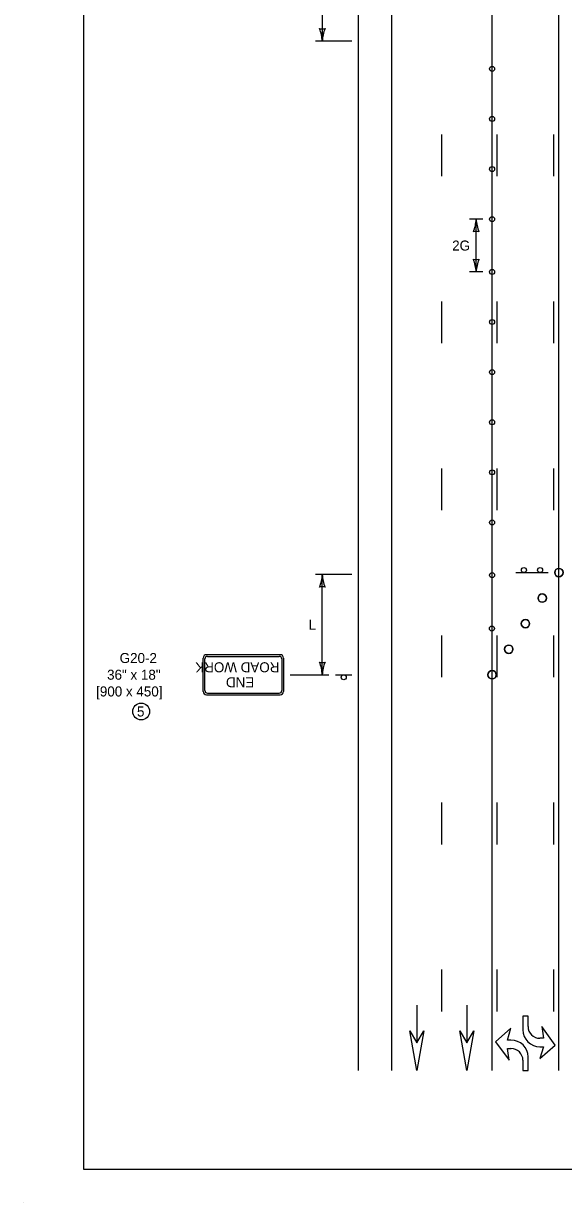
# Model space of a CAD drawing. Extents: x 49991.4 to 50021, y 49987.6 to 50011.4.
# Drawn here: x 49999.98 to 50003.21, y 49999.86 to 50006.92 of the extents above; entities that cross this region are included whole.
import ezdxf

# ---------------------------------------------------------------- set-up
doc = ezdxf.new("R2010")
doc.units = 0
for name, color, linetype in [('Level 1', 7, 'Continuous'), ('Level 2', 7, 'Continuous'), ('Level 3', 7, 'Continuous')]:
    doc.layers.add(name, color=color, linetype=linetype)

msp = doc.modelspace()

# ---------------------------------------------------------------- linework, layer by layer
at = {"layer": 'Level 1'}
for p, q in [((50001.9802, 50000.6526), (50001.9802, 50009.1708)), ((50002.1802, 50000.6526), (50002.1802, 50009.1708)), ((50002.7802, 50000.6526), (50002.7802, 50009.1708)), ((50003.1802, 50000.6526), (50003.1802, 50009.1708)), ((50002.4803, 50006.0059), (50002.4803, 50006.2559)), ((50002.8102, 50006.0059), (50002.8102, 50006.2559)), ((50003.1502, 50006.0059), (50003.1502, 50006.2559)), ((50002.4803, 50005.0059), (50002.4803, 50005.2559)), ((50002.8102, 50005.0059), (50002.8102, 50005.2559)), ((50003.1502, 50005.0059), (50003.1502, 50005.2559)), ((50002.4803, 50004.0059), (50002.4803, 50004.2559)), ((50002.8102, 50004.0059), (50002.8102, 50004.2559)), ((50003.1502, 50004.0059), (50003.1502, 50004.2559)), ((50002.9232, 50003.6329), (50003.0192, 50003.6329)), ((50003.0192, 50003.6329), (50003.1152, 50003.6329)), ((50002.4803, 50003.0059), (50002.4803, 50003.2559)), ((50002.8102, 50003.0059), (50002.8102, 50003.2559)), ((50003.1502, 50003.0059), (50003.1502, 50003.2559)), ((50001.0516, 50002.9214), (50001.0516, 50003.1214)), ((50001.0616, 50002.9264), (50001.0616, 50003.1164)), ((50001.0718, 50003.1415), (50001.5118, 50003.1415)), ((50001.0766, 50003.1314), (50001.5066, 50003.1314)), ((50001.5216, 50003.1164), (50001.5216, 50002.9264)), ((50001.5316, 50003.1214), (50001.5316, 50002.9214)), ((50001.8442, 50003.0214), (50001.9402, 50003.0214)), ((50001.0716, 50002.9014), (50001.5116, 50002.9014)), ((50001.0766, 50002.9114), (50001.5066, 50002.9114)), ((50002.4803, 50002.0059), (50002.4803, 50002.2559)), ((50002.4803, 50002.0059), (50002.4803, 50002.2559)), ((50002.8102, 50002.0059), (50002.8102, 50002.2559)), ((50002.8102, 50002.0059), (50002.8102, 50002.2559)), ((50003.1502, 50002.0059), (50003.1502, 50002.2559)), ((50003.1502, 50002.0059), (50003.1502, 50002.2559)), ((50002.4803, 50001.0059), (50002.4803, 50001.2559)), ((50002.4803, 50001.0059), (50002.4803, 50001.2559)), ((50002.8102, 50001.0059), (50002.8102, 50001.2559)), ((50002.8102, 50001.0059), (50002.8102, 50001.2559)), ((50003.1502, 50001.0059), (50003.1502, 50001.2559)), ((50003.1502, 50001.0059), (50003.1502, 50001.2559)), ((50002.3301, 50001.0427), (50002.3301, 50000.8168)), ((50002.3305, 50001.0427), (50002.3305, 50000.8168)), ((50002.6295, 50001.0427), (50002.6295, 50000.8168)), ((50002.6299, 50001.0427), (50002.6299, 50000.8168)), ((50002.9955, 50000.9766), (50002.9649, 50000.9766)), ((50002.9649, 50000.9766), (50002.9649, 50000.8957)), ((50002.9955, 50000.9159), (50002.9955, 50000.9766)), ((50002.8934, 50000.9053), (50002.8015, 50000.8244)), ((50002.873, 50000.8345), (50002.8934, 50000.9053)), ((50003.1588, 50000.8047), (50003.0772, 50000.9159)), ((50003.0772, 50000.9159), (50003.0874, 50000.8452)), ((50002.8934, 50000.8345), (50002.873, 50000.8345)), ((50003.0609, 50000.8502), (50003.0609, 50000.8502)), ((50003.0874, 50000.8452), (50003.067, 50000.8452)), ((50002.8015, 50000.8244), (50002.8832, 50000.7132)), ((50002.8832, 50000.7132), (50002.873, 50000.784)), ((50002.873, 50000.784), (50002.8934, 50000.784)), ((50002.8995, 50000.7789), (50002.8995, 50000.7789)), ((50003.067, 50000.7239), (50003.1588, 50000.8047)), ((50003.067, 50000.7946), (50003.0874, 50000.7946)), ((50003.0874, 50000.7946), (50003.067, 50000.7239)), ((50002.9649, 50000.7132), (50002.9649, 50000.6526)), ((50002.9955, 50000.6526), (50002.9955, 50000.7334)), ((50002.9649, 50000.6526), (50002.9955, 50000.6526)), ((49999.9766, 49999.8624), (49999.9766, 49999.8624))]:
    msp.add_line(p, q, dxfattribs=at)
for points in [[(50008.6146, 50011.2628), (50000.3356, 50011.2628), (50000.3356, 50000.0624), (50008.6146, 50000.0624)], [(50002.3721, 50000.8891), (50002.3305, 50000.6526), (50002.2885, 50000.8891), (50002.3305, 50000.8169)], [(50002.6715, 50000.8891), (50002.6299, 50000.6526), (50002.5879, 50000.8891), (50002.6299, 50000.8169)]]:
    msp.add_lwpolyline(points, close=True, dxfattribs=at)
for centre, radius in [((50002.7802, 50006.6484), 0.015), ((50002.7802, 50006.3484), 0.015), ((50002.7802, 50006.0484), 0.015), ((50002.7802, 50005.7484), 0.015), ((50002.7802, 50005.4329), 0.015), ((50002.7802, 50005.1329), 0.015), ((50002.7802, 50004.8329), 0.015), ((50002.7802, 50004.5329), 0.015), ((50002.7802, 50004.2329), 0.015), ((50002.7802, 50003.9329), 0.015), ((50002.9712, 50003.6481), 0.0152), ((50003.0672, 50003.6481), 0.0152), ((50003.1802, 50003.6329), 0.025), ((50002.7802, 50003.6174), 0.015), ((50003.0802, 50003.48), 0.025), ((50002.7796, 50003.2979), 0.015), ((50002.9802, 50003.3272), 0.025), ((50002.8802, 50003.1743), 0.025), ((50001.8922, 50003.0063), 0.0152), ((50002.7802, 50003.0214), 0.025)]:
    msp.add_circle(centre, radius, dxfattribs=at)
for centre, radius, start, end in [((50003.1802, 50003.6329), 0.025, 0, 180), ((50003.1802, 50003.6329), 0.025, 180, 0), ((50003.0802, 50003.48), 0.025, 0, 180), ((50003.0802, 50003.48), 0.025, 180, 0), ((50002.9802, 50003.3272), 0.025, 0, 180), ((50002.9802, 50003.3272), 0.025, 180, 0), ((50002.8802, 50003.1743), 0.025, 0, 180), ((50002.8802, 50003.1743), 0.025, 180, 0), ((50001.0718, 50003.1214), 0.02, 90, 180), ((50001.0766, 50003.1164), 0.015, 90, 180), ((50001.5066, 50003.1164), 0.015, 360, 90), ((50001.5118, 50003.1214), 0.02, 360, 90), ((50002.7802, 50003.0214), 0.025, 0, 180), ((50002.7802, 50003.0214), 0.025, 180, 0), ((50001.0716, 50002.9214), 0.02, 180, 270), ((50001.0766, 50002.9264), 0.015, 180, 270), ((50001.5066, 50002.9264), 0.015, 270, 360), ((50001.5116, 50002.9214), 0.02, 270, 360)]:
    msp.add_arc(centre, radius, start, end, dxfattribs=at)
for centre, major_axis in [((50003.067, 50000.8957), (-0.1021, 0)), ((50003.067, 50000.9159), (-0.0715, 0)), ((50002.8934, 50000.7334), (0.1021, 0)), ((50002.8934, 50000.7132), (0.0715, 0))]:
    msp.add_ellipse(centre, major_axis=major_axis, ratio=0.990099, start_param=0, end_param=1.570796, dxfattribs=at)
at = {"layer": 'Level 2'}
msp.add_circle((50000.6801, 50002.8013), 0.0501, dxfattribs=at)
at = {"layer": 'Level 3'}
for p, q in [((50001.7642, 50007.2639), (50001.7642, 50006.8139)), ((50001.9402, 50006.8139), (50001.7242, 50006.8139)), ((50002.7252, 50005.7484), (50002.6452, 50005.7484)), ((50002.6852, 50005.4329), (50002.6852, 50005.7484)), ((50002.7252, 50005.4329), (50002.6452, 50005.4329)), ((50001.9402, 50003.6214), (50001.7242, 50003.6214)), ((50001.7642, 50003.0214), (50001.7642, 50003.6214)), ((50001.5716, 50003.0214), (50001.8042, 50003.0214))]:
    msp.add_line(p, q, dxfattribs=at)
for centre, radius, start, end in [((50001.7642, 50006.9421), 0.0548, 252.13882, 287.86118), ((50001.5315, 50006.8024), 0.233, 2.82731, 22.07716), ((50001.9863, 50006.8047), 0.2223, 157.45601, 177.63952), ((50002.4631, 50005.7575), 0.2223, 337.45601, 357.63952), ((50002.9179, 50005.7599), 0.233, 182.82731, 202.07716), ((50002.6852, 50005.6202), 0.0548, 72.13882, 107.86118), ((50002.6852, 50005.5611), 0.0548, 252.13882, 287.86118), ((50002.4525, 50005.4214), 0.233, 2.82731, 22.07716), ((50002.9073, 50005.4238), 0.2223, 157.45601, 177.63952), ((50001.5421, 50003.6306), 0.2223, 337.45601, 357.63952), ((50001.9969, 50003.6329), 0.233, 182.82731, 202.07716), ((50001.7642, 50003.4932), 0.0548, 72.13882, 107.86118), ((50001.7642, 50003.1496), 0.0548, 252.13882, 287.86118), ((50001.5315, 50003.0099), 0.233, 2.82731, 22.07716), ((50001.9863, 50003.0123), 0.2223, 157.45601, 177.63952)]:
    msp.add_arc(centre, radius, start, end, dxfattribs=at)

# ---------------------------------------------------------------- texts
at = {"layer": 'Level 1'}
for s, p in [('ROAD WORK', (50001.5075, 50003.0961)), ('END', (50001.3569, 50003.0061))]:
    msp.add_text(s, height=0.06, rotation=180, dxfattribs=at).set_placement(p)
at = {"layer": 'Level 2'}
for s, p in [('2G', (50002.5415, 50005.5606)), ('L', (50001.6818, 50003.2914)), ('G20-2', (50000.5516, 50003.0914)), ('36" x 18"', (50000.4764, 50002.9914)), ('[900 x 450]', (50000.4108, 50002.8914)), ('5', (50000.6552, 50002.7713))]:
    msp.add_text(s, height=0.06, dxfattribs=at).set_placement(p)

doc.saveas('drawing.dxf')
